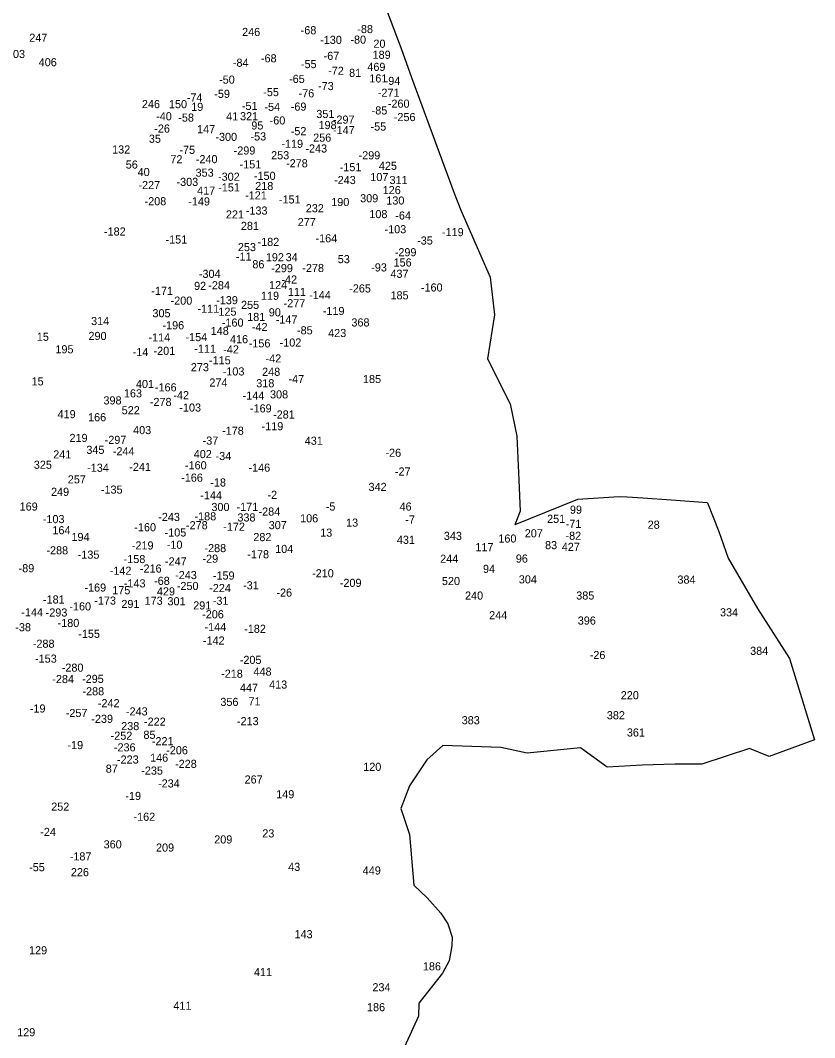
# Model space of a CAD drawing. Extents: x -784109 to -782312, y -974244 to -970866.
# Drawn here: x -782876 to -782312, y -973653 to -972930 of the extents above; entities that cross this region are included whole.
import ezdxf

# ---------------------------------------------------------------- set-up
doc = ezdxf.new("R2010")
doc.units = 0
doc.layers.add('Vrstva 13', color=7, linetype='Continuous')
doc.layers.add('Vrstva 24', color=7, linetype='Continuous')

msp = doc.modelspace()

# ---------------------------------------------------------------- linework, layer by layer
at = {"layer": 'Vrstva 13'}
for p, q in [((-782628.66, -972888.81), (-782605.57, -972949.88)), ((-782605.57, -972949.88), (-782598.12, -972970.59)), ((-782598.12, -972970.59), (-782580.32, -973019.48)), ((-782580.32, -973019.48), (-782567.89, -973052.72)), ((-782567.89, -973052.72), (-782563.09, -973064.86)), ((-782563.09, -973064.86), (-782542.33, -973112.57)), ((-782542.33, -973112.57), (-782539.23, -973139.18)), ((-782539.23, -973139.18), (-782544.09, -973170.46)), ((-782544.09, -973170.46), (-782528.05, -973202.56)), ((-782528.05, -973202.56), (-782523.29, -973225.64)), ((-782523.29, -973225.64), (-782521.94, -973256.92)), ((-782521.94, -973256.92), (-782520.91, -973278.94)), ((-782480.17, -973270.58), (-782524.69, -973288.57)), ((-782450.66, -973268.69), (-782480.17, -973270.58)), ((-782444.97, -973268.79), (-782450.66, -973268.69)), ((-782433.89, -973269.52), (-782444.97, -973268.79)), ((-782413.7, -973271.12), (-782433.89, -973269.52)), ((-782387.86, -973272.85), (-782413.7, -973271.12)), ((-782387.86, -973272.85), (-782379.89, -973293.35)), ((-782520.91, -973278.94), (-782524.69, -973288.57)), ((-782379.89, -973293.35), (-782373.16, -973312.3)), ((-782373.16, -973312.3), (-782352.25, -973348.16)), ((-782352.25, -973348.16), (-782329.58, -973383.53)), ((-782329.58, -973383.53), (-782311.72, -973441.42)), ((-782575.99, -973445.47), (-782587.33, -973455.62)), ((-782534.64, -973446.78), (-782575.99, -973445.47)), ((-782311.72, -973441.42), (-782344.07, -973453.25)), ((-782515.9, -973450.82), (-782534.64, -973446.78)), ((-782478.07, -973447.07), (-782515.9, -973450.82)), ((-782459.08, -973460.91), (-782478.07, -973447.07)), ((-782358.05, -973447.66), (-782391.79, -973458.74)), ((-782344.07, -973453.25), (-782358.05, -973447.66)), ((-782587.33, -973455.62), (-782599.6, -973474.2)), ((-782434.34, -973459.36), (-782459.08, -973460.91)), ((-782411.15, -973458.64), (-782434.34, -973459.36)), ((-782391.79, -973458.74), (-782411.15, -973458.64)), ((-782599.6, -973474.2), (-782605.86, -973490.17)), ((-782605.86, -973490.17), (-782599.65, -973508.61)), ((-782599.65, -973508.61), (-782596.61, -973544.63)), ((-782596.61, -973544.63), (-782586.98, -973553.74)), ((-782586.98, -973553.74), (-782577.46, -973564.56)), ((-782577.46, -973564.56), (-782572.33, -973572.33)), ((-782572.33, -973572.33), (-782569.22, -973581.76)), ((-782569.22, -973581.76), (-782569.53, -973587.77)), ((-782569.53, -973587.77), (-782571.49, -973598.42)), ((-782571.49, -973598.42), (-782576.15, -973607.38)), ((-782576.15, -973607.38), (-782593.07, -973628.56)), ((-782593.07, -973628.56), (-782593.28, -973637.78)), ((-782593.28, -973637.78), (-782606.89, -973667.99))]:
    msp.add_line(p, q, dxfattribs=at)

# ---------------------------------------------------------------- texts
at = {"layer": 'Vrstva 24'}
for s, p in [('-88', (-782636.707, -972938.985)), ('247', (-782869.831, -972945.162)), ('246', (-782718.572, -972941.042)), ('-68', (-782676.972, -972939.815)), ('-130', (-782663.148, -972946.673)), ('-80', (-782641.626, -972946.497)), ('20', (-782625.269, -972949.422)), ('303', (-782885.699, -972956.702)), ('-68', (-782705.208, -972959.769)), ('-67', (-782660.659, -972958.025)), ('189', (-782625.869, -972957.262)), ('406', (-782863.149, -972962.572)), ('-84', (-782725.154, -972962.937)), ('-55', (-782676.801, -972963.891)), ('469', (-782629.595, -972965.842)), ('-50', (-782734.948, -972974.933)), ('-65', (-782685.224, -972974.423)), ('-72', (-782657.451, -972968.639)), ('81', (-782642.565, -972970.112)), ('161', (-782628.201, -972974.072)), ('-73', (-782664.633, -972979.491)), ('-94', (-782617.286, -972975.827)), ('-74', (-782757.917, -972987.635)), ('-59', (-782738.358, -972985.025)), ('-55', (-782703.541, -972983.787)), ('-76', (-782678.455, -972984.653)), ('-271', (-782622.142, -972984.247)), ('246', (-782789.802, -972992.322)), ('150', (-782770.562, -972992.362)), ('19', (-782754.769, -972994.312)), ('-51', (-782718.758, -972993.609)), ('-54', (-782702.716, -972994.325)), ('-69', (-782684.034, -972994.121)), ('-85', (-782626.519, -972996.821)), ('-260', (-782615.028, -972992.017)), ('-40', (-782779.68, -973000.977)), ('-58', (-782763.941, -973001.931)), ('41', (-782729.921, -973001.072)), ('321', (-782720.055, -973000.932)), ('-60', (-782699.024, -973003.941)), ('351', (-782665.855, -972999.352)), ('-297', (-782654.121, -973003.355)), ('-256', (-782610.79, -973001.553)), ('-26', (-782781.009, -973009.729)), ('147', (-782750.573, -973010.132)), ('95', (-782712.046, -973007.512)), ('198', (-782664.279, -973007.222)), ('-147', (-782653.976, -973010.825)), ('-55', (-782627.317, -973008.293)), ('35', (-782784.833, -973016.972)), ('-300', (-782737.575, -973015.651)), ('-53', (-782712.627, -973015.317)), ('-52', (-782684.045, -973011.569)), ('256', (-782668.096, -973016.172)), ('132', (-782810.955, -973024.592)), ('-75', (-782763.143, -973024.851)), ('-299', (-782724.598, -973025.301)), ('-119', (-782690.672, -973020.531)), ('-243', (-782673.604, -973023.881)), ('72', (-782769.555, -973031.562)), ('-240', (-782751.468, -973031.465)), ('253', (-782697.963, -973028.692)), ('-299', (-782635.833, -973028.733)), ('56', (-782801.266, -973035.312)), ('-151', (-782720.406, -973035.161)), ('-278', (-782687.366, -973034.401)), ('-151', (-782649.236, -973037.147)), ('425', (-782621.398, -973036.202)), ('40', (-782792.815, -973040.622)), ('353', (-782751.653, -973041.072)), ('-302', (-782735.704, -973043.973)), ('-150', (-782710.194, -973043.321)), ('-243', (-782653.246, -973046.307)), ('107', (-782627.474, -973044.182)), ('311', (-782613.828, -973046.302)), ('-227', (-782792.273, -973049.909)), ('-303', (-782765.214, -973047.633)), ('417', (-782750.563, -973053.842)), ('-151', (-782735.592, -973051.553)), ('218', (-782709.275, -973050.542)), ('126', (-782618.689, -973053.452)), ('-208', (-782787.896, -973061.377)), ('-149', (-782756.839, -973061.513)), ('-121', (-782716.446, -973057.213)), ('-151', (-782692.438, -973060.123)), ('190', (-782655.265, -973061.952)), ('309', (-782634.693, -973059.272)), ('130', (-782616.122, -973060.872)), ('-133', (-782715.954, -973068.027)), ('232', (-782673.353, -973066.382)), ('221', (-782730.095, -973070.772)), ('277', (-782679.067, -973076.172)), ('108', (-782628.172, -973070.542)), ('-64', (-782609.705, -973071.55)), ('-182', (-782816.748, -973082.899)), ('281', (-782719.455, -973078.912)), ('-103', (-782617.363, -973081.292)), ('-119', (-782576.548, -973083.337)), ('-151', (-782773.01, -973088.605)), ('-182', (-782707.61, -973090.293)), ('-164', (-782666.412, -973087.76)), ('-35', (-782594.21, -973089.328)), ('253', (-782721.583, -973093.982)), ('-299', (-782610.113, -973097.623)), ('-11', (-782723.025, -973100.746)), ('192', (-782701.729, -973101.212)), ('34', (-782687.618, -973101.142)), ('53', (-782650.613, -973102.552)), ('156', (-782610.948, -973104.926)), ('86', (-782711.316, -973106.192)), ('-299', (-782697.916, -973108.956)), ('-278', (-782675.812, -973108.846)), ('-93', (-782626.843, -973108.436)), ('-304', (-782749.316, -973113)), ('-42', (-782690.665, -973117.046)), ('437', (-782613.191, -973112.962)), ('-171', (-782783.094, -973125.125)), ('92', (-782752.706, -973121.572)), ('-284', (-782742.639, -973121.13)), ('124', (-782699.421, -973121.012)), ('111', (-782686.091, -973125.852)), ('-265', (-782642.473, -973123.366)), ('-160', (-782591.541, -973122.698)), ('-200', (-782769.417, -973132.055)), ('-139', (-782737.03, -973131.74)), ('119', (-782705.191, -973128.592)), ('-277', (-782689.1, -973133.91)), ('-144', (-782670.97, -973128.11)), ('185', (-782613.145, -973128.282)), ('305', (-782782.299, -973140.992)), ('-111', (-782750.314, -973137.77)), ('125', (-782735.435, -973139.902)), ('255', (-782719.353, -973135.082)), ('90', (-782699.643, -973140.332)), ('-119', (-782661.235, -973139.422)), ('314', (-782825.891, -973146.562)), ('-160', (-782732.984, -973147.662)), ('181', (-782714.998, -973143.632)), ('-147', (-782694.697, -973145.473)), ('368', (-782640.906, -973147.562)), ('-196', (-782775.196, -973149.571)), ('148', (-782740.911, -973153.592)), ('-42', (-782711.654, -973150.793)), ('-85', (-782679.568, -973153.162)), ('423', (-782657.448, -973155.072)), ('15', (-782864.485, -973157.732)), ('290', (-782827.763, -973157.162)), ('-114', (-782785.124, -973158.169)), ('-154', (-782758.82, -973157.98)), ('416', (-782727.195, -973159.462)), ('-156', (-782713.886, -973162.425)), ('-102', (-782691.933, -973161.828)), ('195', (-782851.249, -973166.632)), ('-14', (-782796.336, -973168.591)), ('-201', (-782781.544, -973167.737)), ('-111', (-782752.532, -973166.216)), ('-42', (-782732.008, -973166.742)), ('-115', (-782742.106, -973174.488)), ('-42', (-782701.922, -973173.158)), ('273', (-782755.025, -973179.342)), ('-103', (-782732.372, -973182.374)), ('248', (-782704.358, -973182.642)), ('15', (-782868.185, -973189.442)), ('401', (-782794.037, -973191.322)), ('274', (-782741.851, -973190.252)), ('318', (-782708.535, -973190.782)), ('-47', (-782685.624, -973187.788)), ('185', (-782632.695, -973187.782)), ('163', (-782802.589, -973197.972)), ('-166', (-782780.542, -973193.696)), ('-42', (-782767.432, -973199.272)), ('308', (-782698.749, -973198.702)), ('398', (-782817.106, -973202.972)), ('-278', (-782784.164, -973204.092)), ('-144', (-782718.206, -973199.572)), ('419', (-782849.725, -973212.762)), ('522', (-782804.163, -973209.982)), ('-103', (-782763.196, -973208.072)), ('-169', (-782713.012, -973208.65)), ('-281', (-782696.594, -973213.01)), ('166', (-782828.043, -973214.942)), ('403', (-782796.045, -973224.082)), ('-178', (-782732.806, -973224.528)), ('-119', (-782704.731, -973221.364)), ('219', (-782841.249, -973229.662)), ('-297', (-782816.245, -973231.008)), ('-37', (-782746.63, -973231.568)), ('431', (-782674.081, -973231.652)), ('241', (-782852.841, -973241.402)), ('345', (-782829.278, -973238.102)), ('-244', (-782810.461, -973239.148)), ('402', (-782752.955, -973241.152)), ('-34', (-782737.448, -973242.545)), ('-26', (-782616.715, -973240.21)), ('325', (-782866.613, -973248.712)), ('-160', (-782759.194, -973249.106)), ('-134', (-782828.72, -973250.862)), ('-241', (-782798.754, -973250.254)), ('-146', (-782714.062, -973250.804)), ('-27', (-782610.001, -973253.521)), ('257', (-782842.455, -973259.112)), ('-166', (-782761.88, -973257.9)), ('-18', (-782741.202, -973261.33)), ('342', (-782628.748, -973264.482)), ('249', (-782854.372, -973267.962)), ('-135', (-782818.956, -973266.406)), ('-144', (-782748.295, -973270.442)), ('-2', (-782700.595, -973270.096)), ('169', (-782876.693, -973278.442)), ('300', (-782740.406, -973278.742)), ('-171', (-782722.555, -973278.686)), ('-5', (-782659.152, -973278.408)), ('46', (-782606.692, -973278.462)), ('-243', (-782778.201, -973285.85)), ('-188', (-782752.414, -973285.392)), ('338', (-782721.923, -973286.202)), ('-284', (-782706.916, -973282)), ('99', (-782485.619, -973280.682)), ('-103', (-782860.208, -973287.368)), ('-160', (-782795.174, -973293.15)), ('-278', (-782758.454, -973291.722)), ('-172', (-782731.995, -973292.78)), ('307', (-782699.701, -973291.622)), ('106', (-782677.365, -973286.792)), ('13', (-782644.695, -973289.882)), ('-7', (-782602.617, -973287.687)), ('251', (-782501.855, -973287.152)), ('-71', (-782488.63, -973290.737)), ('28', (-782430.403, -973291.372)), ('164', (-782853.405, -973295.272)), ('194', (-782839.855, -973300.072)), ('-105', (-782773.671, -973296.877)), ('282', (-782710.603, -973300.162)), ('13', (-782663.115, -973296.992)), ('343', (-782575.228, -973299.302)), ('207', (-782517.731, -973297.462)), ('-82', (-782488.759, -973299.213)), ('-219', (-782796.944, -973306.099)), ('-10', (-782772.123, -973305.595)), ('431', (-782608.611, -973302.092)), ('117', (-782552.81, -973307.292)), ('160', (-782536.485, -973301.172)), ('83', (-782503.283, -973305.882)), ('427', (-782491.421, -973307.122)), ('-288', (-782857.649, -973309.558)), ('-135', (-782835.42, -973312.634)), ('-288', (-782745.349, -973307.983)), ('-178', (-782714.864, -973312.368)), ('104', (-782695.087, -973308.582)), ('-89', (-782877.423, -973322.292)), ('-158', (-782802.762, -973315.772)), ('-247', (-782773.394, -973317.423)), ('-29', (-782746.742, -973315.503)), ('244', (-782577.834, -973315.562)), ('96', (-782524.089, -973315.422)), ('-142', (-782812.652, -973324.068)), ('-216', (-782791.222, -973322.515)), ('-243', (-782766.178, -973327.165)), ('-159', (-782739.357, -973327.504)), ('-210', (-782668.883, -973325.884)), ('94', (-782547.412, -973322.732)), ('-169', (-782830.647, -973336.032)), ('-143', (-782802.626, -973333.044)), ('-68', (-782781.151, -973331.259)), ('-250', (-782764.984, -973334.911)), ('-224', (-782741.97, -973336.362)), ('-31', (-782717.911, -973334.448)), ('-209', (-782649.161, -973332.686)), ('520', (-782576.599, -973331.392)), ('304', (-782521.955, -973330.212)), ('384', (-782409.238, -973330.362)), ('175', (-782810.867, -973337.932)), ('429', (-782779.132, -973338.752)), ('-26', (-782694.225, -973339.614)), ('240', (-782560.165, -973341.742)), ('385', (-782481.153, -973341.692)), ('-181', (-782860.098, -973344.5)), ('-160', (-782841.348, -973349.426)), ('-173', (-782823.625, -973345.284)), ('291', (-782804.399, -973347.722)), ('173', (-782787.877, -973345.392)), ('301', (-782771.622, -973345.772)), ('291', (-782753.349, -973348.752)), ('-31', (-782739.428, -973345.428)), ('-144', (-782875.483, -973353.582)), ('-293', (-782858.19, -973353.75)), ('-206', (-782746.988, -973355.03)), ('244', (-782543.034, -973355.732)), ('334', (-782378.978, -973353.632)), ('-38', (-782879.778, -973364.238)), ('-180', (-782849.696, -973361.21)), ('-144', (-782745.307, -973364.106)), ('-182', (-782717.112, -973365.358)), ('396', (-782480.059, -973359.502)), ('-155', (-782835.022, -973368.926)), ('-288', (-782867.303, -973375.962)), ('-142', (-782746.42, -973373.682)), ('-153', (-782865.745, -973386.552)), ('-205', (-782720.244, -973387.458)), ('-26', (-782471.557, -973383.985)), ('384', (-782357.568, -973381.022)), ('-280', (-782846.759, -973392.982)), ('-284', (-782853.458, -973401.082)), ('-295', (-782832.326, -973400.962)), ('-218', (-782733.488, -973397.282)), ('448', (-782710.504, -973395.772)), ('447', (-782720.136, -973407.252)), ('413', (-782699.391, -973404.982)), ('-288', (-782832.043, -973409.782)), ('220', (-782449.499, -973412.592)), ('-19', (-782869.441, -973421.995)), ('-242', (-782821.09, -973418.223)), ('356', (-782734.036, -973417.322)), ('71', (-782714.087, -973416.932)), ('-257', (-782843.921, -973425.217)), ('-239', (-782825.732, -973429.347)), ('-243', (-782801.142, -973424.075)), ('383', (-782562.533, -973430.352)), ('382', (-782459.403, -973426.802)), ('238', (-782804.523, -973434.532)), ('-222', (-782788.305, -973431.345)), ('-213', (-782722.26, -973431)), ('-252', (-782812.015, -973441.343)), ('85', (-782788.703, -973440.702)), ('-221', (-782782.728, -973445.253)), ('361', (-782445.159, -973439.062)), ('-19', (-782842.702, -973448.034)), ('-236', (-782809.698, -973449.633)), ('-206', (-782772.53, -973451.703)), ('-223', (-782807.505, -973458.305)), ('146', (-782783.955, -973456.972)), ('87', (-782815.475, -973464.792)), ('-235', (-782790.253, -973466.171)), ('-228', (-782766.245, -973461.371)), ('120', (-782632.522, -973463.472)), ('267', (-782716.828, -973472.472)), ('-234', (-782778.318, -973475.281)), ('-19', (-782801.545, -973484.163)), ('149', (-782694.355, -973482.982)), ('252', (-782854.243, -973491.792)), ('-162', (-782795.761, -973498.983)), ('-24', (-782862.042, -973509.784)), ('209', (-782738.403, -973515.112)), ('23', (-782704.253, -973510.792)), ('360', (-782816.993, -973518.592)), ('209', (-782779.783, -973520.882)), ('-187', (-782841.078, -973527.159)), ('-55', (-782869.942, -973534.818)), ('226', (-782840.276, -973538.362)), ('43', (-782685.858, -973534.582)), ('449', (-782632.877, -973537.172)), ('143', (-782681.351, -973582.472)), ('129', (-782869.999, -973593.892)), ('411', (-782710.173, -973609.402)), ('186', (-782590.129, -973605.332)), ('234', (-782625.998, -973620.202)), ('411', (-782767.403, -973633.302)), ('186', (-782629.839, -973634.352)), ('129', (-782878.439, -973652.172))]:
    msp.add_text(s, height=5.76, dxfattribs=at).set_placement(p)

doc.saveas('drawing.dxf')
